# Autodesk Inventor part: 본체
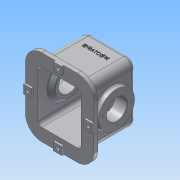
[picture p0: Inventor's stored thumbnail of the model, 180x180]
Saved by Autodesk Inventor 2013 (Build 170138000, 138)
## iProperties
Created: 2014-11
Part Number: 본체
Material: Aluminum 6061
Document SubType Name: Modeling
Designer: Administrator
Density: 2.71 g/cm^3
Mass: 2888.28 g
Surface Area: 2081.98 cm^2
Volume: 1065.78 cm^3
Author: Administrator
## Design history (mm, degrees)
sketch "Sketch1"
  geometry: L1 (65, 59)-(-65, 59); L2 (-65, 59)-(-65, -59); L3 (-65, -59)-(65, -59); L4 (65, -59)-(65, 59); L5 (65, 59)-(-65, -59); L6 (-65, 59)-(65, -59); 4 further points
  constraints: 12 end point, 4 midpoint, 2 coincident, 2 parallel, 1 horizontal, 1 perpendicular
  dimensions: "d0" = 130 distance of L3.end L2.end; "d1" = 118 distance of L2.end L1.end
extrude "Extrusion1" new body sketch "Sketch1" stored distance "d2" = 152; taper "d3" = 0 deg
sketch "Sketch6"
  geometry: L1 (-69, -98)-(-59, -98); L2 (-59, -98)-(-59, 98); L3 (-59, 98)-(-69, 98); L4 (-69, 98)-(-69, -98); L5 (-69, -98)-(-59, 98); L6 (-59, -98)-(-69, 98); L7 (59, -76)-(-59, -76) reference; L8 (-59, -76)-(-59, 76) reference; L9 (-59, 76)-(59, 76) reference; L10 (59, 76)-(59, -76) reference; 4 further points
  constraints: 12 end point, 4 midpoint, 2 coincident, 2 parallel, 1 horizontal, 1 perpendicular
  dimensions: "d28" = 196 distance of L3.end L1.start; "d30" = 10 distance of L2.end L3.end
extrude "Extrusion5" join sketch "Sketch6" stored distance "d31" = 174; taper "d32" = 0 deg
sketch "Sketch7"
  geometry: L1 (-69, -98)-(-69, 98) reference; C1 r 45.5 at (-1, 0); 2 further points
  constraints: 1 centre point, 1 horizontal alignment, 1 midpoint
  dimensions: "d33" = 91 diameter of C1; "d34" = 68 distance of C1.centre point (-69, 0)
extrude "Extrusion6" join sketch "Sketch7" stored distance "d35" = 154; taper "d36" = 0 deg
sketch "Sketch9"
  geometry: L1 (49, 66)-(-93, 66); L2 (-93, 66)-(-93, -66); L3 (-93, -66)-(49, -66); L4 (49, -66)-(49, 66); L5 (59, -76)-(59, 76) reference; 2 further points
  constraints: 8 end point, 2 parallel, 1 horizontal, 1 horizontal alignment, 1 midpoint, 1 perpendicular
  dimensions: "d40" = 10 distance between parallel lines of L5 L4; "d41" = 132 distance of L3.end L1.start; "d42" = 142 distance of L1.start L1.end
extrude "Extrusion7" cut sketch "Sketch9" stored distance "d43" = 110; taper "d44" = 0 deg
sketch "Sketch10"
  geometry: L1 (-55, 66)-(-55, -66) reference; L2 (-55, -66)-(55, -66) reference; L3 (55, -66)-(55, 66) reference; L4 (55, 66)-(-55, 66) reference; L5 (65, -76)-(-65, -76) reference; L6 (-65, -76)-(-65, -45.489) reference; L7 (-65, -45.489)-(-77, -45.489) reference; L8 (-77, -45.489)-(-77, 45.489) reference; L9 (-77, 45.489)-(-65, 45.489) reference; L10 (-65, 45.489)-(-65, 76) reference; L11 (-65, 76)-(65, 76) reference; L12 (65, 76)-(65, 45.489) reference; L13 (65, 45.489)-(77, 45.489) reference; L14 (77, 45.489)-(77, -45.489) reference; L15 (77, -45.489)-(65, -45.489) reference; L16 (65, -45.489)-(65, -76) reference; L17 (-77, 0)-(-55, 0); L18 (-77, 26)-(-55, 26); 1 further point
  constraints: 4 end point, 2 midpoint, 2 point on line, 1 perpendicular
  dimensions: "d45" = 52 diameter of L18 L17
revolve "Revolution1" sketch "Sketch10" stored, may be unused: angle "d46" = 90 deg
sketch "Sketch11"
  geometry: L1 (65, -76)-(-65, -76) reference; L2 (-65, -76)-(-65, -45.489) reference; L3 (-65, -45.489)-(-77, -45.489) reference; L4 (-77, -45.489)-(-77, -26) reference; L5 (-77, -26)-(-55, -26) reference; L6 (-55, -26)-(-55, -66) reference; L7 (-55, -66)-(55, -66) reference; L8 (55, -66)-(55, 66) reference; L9 (55, 66)-(-55, 66) reference; L10 (-55, 66)-(-55, 26) reference; L11 (-55, 26)-(-77, 26) reference; L12 (-77, 26)-(-77, 45.489) reference; L13 (-77, 45.489)-(-65, 45.489) reference; L14 (-65, 45.489)-(-65, 76) reference; L15 (-65, 76)-(65, 76) reference; L16 (65, 76)-(65, 45.489) reference; L17 (65, 45.489)-(77, 45.489) reference; L18 (77, 45.489)-(77, -45.489) reference; L19 (77, -45.489)-(65, -45.489) reference; L20 (65, -45.489)-(65, -76) reference; L21 (-55, 26)-(-45, 26); L22 (-45, 26)-(-45, 35.5); L23 (-45, 35.5)-(-55, 45.5); L24 (0, 0)-(-92, 0)
  constraints: 8 end point, 3 perpendicular, 1 point on line
  dimensions: "d47" = 10 horizontal distance of L22.end L23.end; "d49" = 71 diameter of L22.end L24; "d50" = 91 diameter of L23.end L24
revolve "Revolution2" sketch "Sketch11" stored, may be unused: angle "d51" = 90 deg
mirror "Mirror2"
fillet "Fillet1" dims "d66" = 42
sketch "Sketch14"
  geometry: L1 (0, 0)-(90, 0) reference; L2 (132, 154)-(132, 42) reference; L3 (0, 196)-(90, 196) reference; L4 (-42, 42)-(-42, 154) reference; 5 further points
  constraints: 2 horizontal alignment, 2 vertical alignment
  dimensions: "d67" = 10 distance from line of point (45, 186) L3; "d68" = 10 distance from line of point (45, 10) L1; "d69" = 10 distance from line of point (-32, 98) L4; "d70" = 10 distance from line of L2 point (122, 98)
hole "Hole2" sketch "Sketch14" at (45, 186), (-32, 98), (45, 10), (122, 98) diameter "d71" = 9; stored, may be unused: countersink angle "d75" = 90 deg, drill point angle "d77" = 118 deg; dims "d72" = 13, "d73" = 14, "d74" = 8.6, "d76" = 16
sketch "Sketch16"
  geometry: L1 (-45, -69)-(45, -69) reference; 3 further points
  constraints: 1 vertical alignment, 1 other
  dimensions: "d89" = 92 distance from line of point (0, 23) L1
emboss "Emboss1" sketch "Sketch16" dims "d0" = 130, "d1" = 118, "d33" = 91, "d34" = 68, "d90" = 1, "d91" = 0
fillet "Fillet2" dims "d92" = 20
fillet "Fillet3" dims "d93" = 10
fillet "Fillet4" dims "d94" = 10
sketch "Sketch17"
  geometry: L1 (-67.6, -81)-(-67.6, -83.5) reference; L2 (-67.6, -83.5)-(-69, -83.5) reference; L3 (-69, -83.5)-(-69, -66) reference; L4 (-69, -66)-(49, -66) reference; L5 (49, -66)-(49, 66) reference; L6 (49, 66)-(-69, 66) reference; L7 (-69, 66)-(-69, 83.5) reference; L8 (-69, 83.5)-(-67.6, 83.5) reference; L9 (-67.6, 83.5)-(-67.6, 81) reference; L10 (-67.6, 81)-(-59, 81) reference; L11 (-59, 81)-(-59, 76) reference; L12 (-59, 76)-(26.153, 76) reference; L13 (26.153, 76)-(26.153, 77) reference; L14 (26.153, 77)-(26.815, 77) reference; L15 (26.815, 77)-(26.815, 76) reference; L16 (26.815, 76)-(49, 76) reference; L17 (59, 66)-(59, -66) reference; L18 (49, -76)-(-59, -76) reference; L19 (-59, -76)-(-59, -81) reference; L20 (-59, -81)-(-67.6, -81) reference; L21 (-69, 98)-(-59, 98) reference; L22 (-59, 98)-(-59, 95) reference; L23 (-59, 95)-(-67.6, 95) reference; L24 (-67.6, 95)-(-67.6, 92.5) reference; L25 (-67.6, 92.5)-(-69, 92.5) reference; L26 (-59, -98)-(-69, -98) reference; L27 (-69, -92.5)-(-67.6, -92.5) reference; L28 (-67.6, -92.5)-(-67.6, -95) reference; L29 (-67.6, -95)-(-59, -95) reference; L30 (-59, -95)-(-59, -98) reference; L31 (0, 0)-(0, 76); L32 (0, 0)-(84.121, 17.88); L33 (-69, -98)-(-69, -92.5) reference; L34 (-69, 92.5)-(-69, 98) reference; A1 r 10 centre (49, 66) between (59, 66) and (49, 76) reference; A2 r 10 centre (49, -66) between (49, -76) and (59, -66) reference; 1 further point
  constraints: 4 end point, 1 coincident, 1 parallel, 1 point on line
  dimensions: "d95" = 78 deg angle of L32 L31; "d96" = 86 distance of L31.start point (84.121, 17.88)
  node "Project Cut Edges6"
workplane "Work Plane2"
  workplane "Work Plane1"
sketch "Sketch19"
  geometry: C1 r 31 at (0, 0); 1 further point
  constraints: 1 centre point, 1 coincident
  dimensions: "d110" = 62 diameter of C1
extrude "Extrusion10" join sketch "Sketch19" stored distance "d112" = 5; taper "d113" = 0 deg
sketch "Sketch20"
  geometry: C1 r 31 at (0, 0) reference; C2 r 21 at (0, 0)
  constraints: 1 centre point, 1 coincident
  dimensions: "d114" = 42 diameter of C2
extrude "Extrusion11" cut sketch "Sketch20" distance "d115" = 25; taper "d116" = 0 deg
sketch "Sketch21"
  geometry: C1 r 21 at (0, 0) reference; C2 r 15 at (0, 0)
  constraints: 1 centre point, 1 coincident
  dimensions: "d117" = 30 diameter of C2
extrude "Extrusion12" cut sketch "Sketch21" stored distance "d118" = 25; taper "d119" = 0 deg
fillet "Fillet5" dims "d120" = 3
chamfer "Chamfer1" distance "d121" = 1; stored, may be unused: second distance "d122" = 2, angle "d123" = 45 deg
fillet "Fillet6" dims "d124" = 0.3
fillet "Fillet7" dims "d125" = 3
sketch "Sketch22"
  geometry: L1 (56, 196)-(34, 196); L2 (34, 196)-(34, 176); L3 (34, 176)-(56, 176); L4 (56, 176)-(56, 196); L5 (56, 196)-(34, 176); L6 (34, 196)-(56, 176); L7 (132, 109)-(112, 109); L8 (112, 109)-(112, 87); L9 (112, 87)-(132, 87); L10 (132, 87)-(132, 109); L11 (132, 109)-(112, 87); L12 (112, 109)-(132, 87); L13 (34, 0)-(56, 0); L14 (56, 0)-(56, 20); L15 (56, 20)-(34, 20); L16 (34, 20)-(34, 0); L17 (34, 0)-(56, 20); L18 (56, 0)-(34, 20); L19 (-42, 109)-(-22, 109); L20 (-22, 109)-(-22, 87); L21 (-22, 87)-(-42, 87); L22 (-42, 87)-(-42, 109); L23 (-42, 109)-(-22, 87); L24 (-22, 109)-(-42, 87); C1 r 4.5 at (45, 186) reference; C2 r 4.5 at (45, 10) reference; C3 r 4.5 at (-32, 98) reference; C4 r 4.5 at (122, 98) reference; 1 further point
  constraints: 48 end point, 8 midpoint, 8 parallel, 4 horizontal, 4 perpendicular
  dimensions: "d126" = 22 distance of L3.end L2.end; "d127" = 20 distance of L2.end L1.end; "d128" = 20 distance of L9.end L8.end; "d129" = 22 distance of L8.end L7.end; "d130" = 22 distance of L15.end L14.end; "d131" = 20 distance of L14.end L13.end; "d132" = 20 distance of L20.end L21.end; "d133" = 22 distance of L19.end L20.end
extrude "Extrusion13" join sketch "Sketch22" distance "d134" = 5; taper "d135" = 0 deg
sketch "Sketch23"
  geometry: C1 r 45.5 at (0, 0) reference; C2 r 27 at (0, 1) reference; 1 further point
  constraints: 1 vertical alignment
  dimensions: "d147" = 35 distance of point (0, 36) C2.centre
hole "Hole5" sketch "Sketch23" at (0, 36) diameter "d137" = 3.242; stored, may be unused: countersink angle "d141" = 90 deg, drill point angle "d143" = 118 deg; dims "d138" = 13, "d139" = 4, "d140" = 2, "d142" = 16
pattern_circular "Circular Pattern5" dims angle "d149" = 360 deg
mirror "Mirror6"
body "Solid1"
node "Project Cut Edges1"
node "Project Cut Edges3"
node "Project Cut Edges4"
other parameters: "d108" = 12 deg, "d109" = 86
